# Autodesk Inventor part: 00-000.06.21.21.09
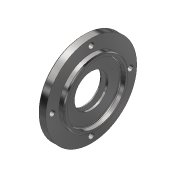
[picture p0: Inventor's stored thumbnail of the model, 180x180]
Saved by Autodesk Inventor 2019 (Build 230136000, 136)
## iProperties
Created: 2019-01
Part Number: 00-000.06.21.21.09
Material: Steel, Mild
Document SubType Name: Modeling
Designer: m.vorobev
Density: 7.85 g/cm^3
Appearance: Semi-Polished
Author: m.vorobev
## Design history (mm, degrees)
derived "00-000.06.21.21.08,09.ipt"
feature "Solid1::00-000.06.21.21.08,09.ipt"
tag "TaggingFeature1"
body "Solid1"
other parameters: "d3" = 52, "d4" = 5, "d5" = 14 deg, "d6" = 69, "d7" = 3.5, "d8" = 12, "d11" = 2, "d12" = 1.5, "d16" = 9, "d21" = 24, "d22" = 118 deg, "d24" = 360 deg
